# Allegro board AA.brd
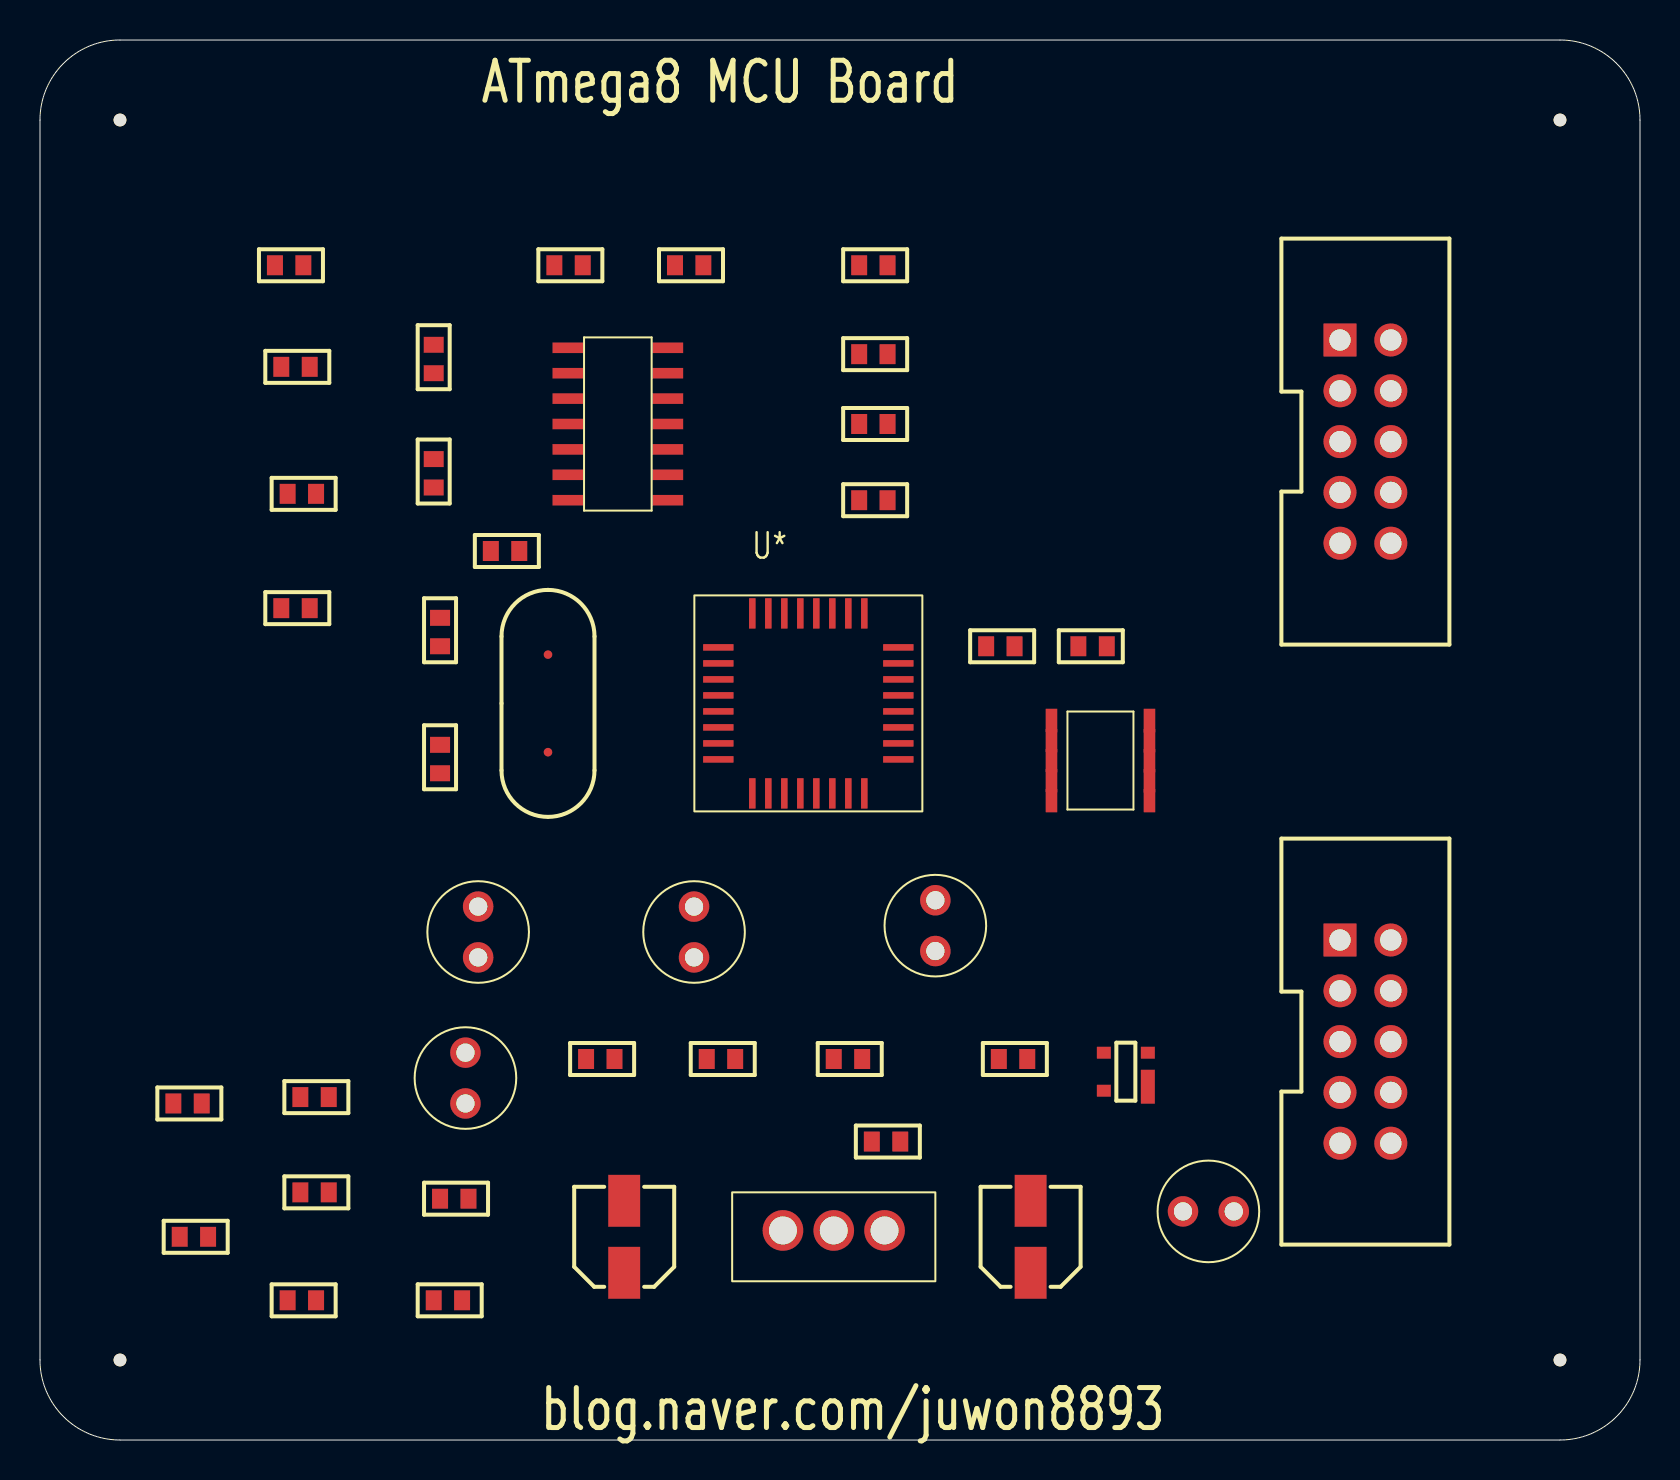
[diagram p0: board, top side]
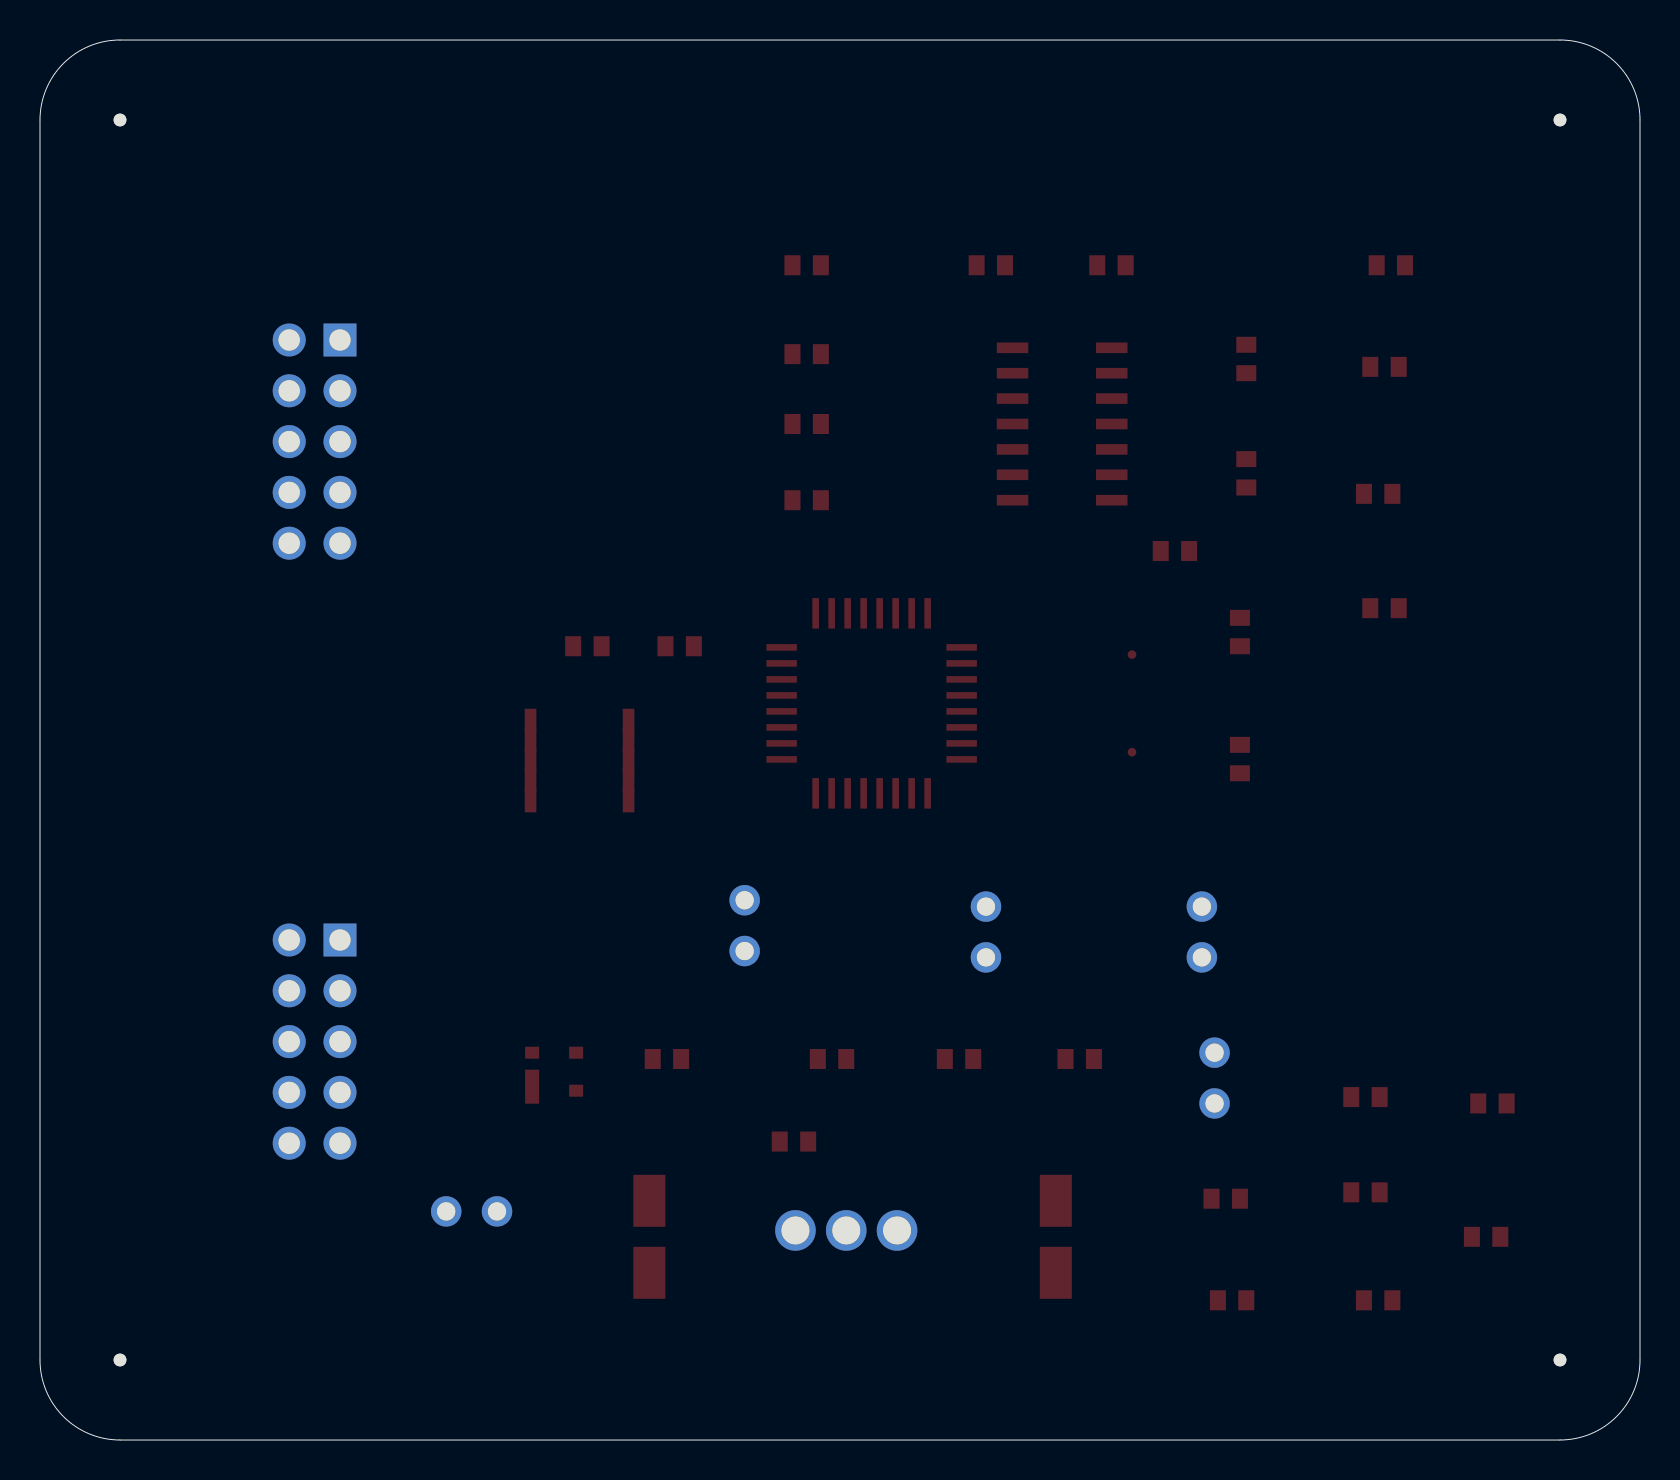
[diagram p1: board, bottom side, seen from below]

Outline 80 x 70 mm; copper layers: TOP, BOTTOM. Coordinates in mm from the lower left corner of the outline.
Outline path: 0,66 0,4 arc(1.17,1.17) 4,0 76,0 arc(78.83,1.17) 80,4 80,66 arc(78.83,68.83) 76,70 4,70 arc(1.17,68.83) 0,66

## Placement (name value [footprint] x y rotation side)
C1  0.1uF  [R]  19.68 53.34 90 top
C2  0.1uF  [R]  19.68 47.62 90 top
C3  220uF/16V  [D55]  49.53 10.16 270 top
C4  220uF/16V  [D55]  29.21 10.16 270 top
D1  LED  [CAP196]  21.91 24.13 0 top
D2  LED  [CAP196]  44.77 24.45 0 top
D3  LED  [CAP196]  32.7 24.13 0 top
D4  LED  [CAP196]  21.27 16.83 0 top
D5  LED  [CAP196]  57.15 11.43 270 top
J1  CON10  [BH2X5]  65 25 0 top
J2  CON10  [BH2X5]  65 55 0 top
NOREF  -  []  4 0 90 top
NOREF#2  -  [unnamed#2]  76 66 0 top
NOREF#3  -  []  76 0 90 top
NOREF#4  -  []  76 66 0 top
NOREF#5  -  []  0 68 0 top
NOREF#6  -  [unnamed#2]  76 4 0 top
NOREF#7  -  [unnamed#2]  4 4 0 top
NOREF#8  -  []  76 0 90 top
NOREF#9  -  [unnamed#2]  4 66 0 top
NOREF#10  -  []  76 66 90 top
R1  1K  [R]  47.94 19.05 0 top
R2  20pF  [R]  20 39.69 90 top
R3  01.uP  [R]  53.34 39.69 180 top
R4  01.uP  [R]  47.31 39.69 0 top
R5  20pF  [R]  20 33.34 90 top
R6  330  [R]  27.3 19.05 0 top
R7  330  [R]  39.69 19.05 0 top
R8  330  [R]  33.34 19.05 0 top
R9  1K  [R]  25.72 58.74 0 top
R10  1K  [R]  31.75 58.74 0 top
R11  1K  [R]  40.96 58.74 0 top
R12  1K  [R]  22.54 44.45 0 top
R13  10  [R]  12.06 53.66 0 top
R14  10  [R]  12.38 47.31 0 top
R15  10  [R]  40.96 46.99 0 top
R16  0.1uF  [R]  40.96 50.8 0 top
R17  100K  [R]  40.96 54.29 0 top
R18  100K  [R]  11.75 58.74 0 top
R19  100K  [R]  12.06 41.59 0 top
R20  0.1uF  [R]  20 12.06 0 top
R21  0.1uF  [R]  19.68 6.99 0 top
R22  0.1uF  [R]  12.38 6.99 0 top
R23  0.1uF  [R]  13.02 12.38 0 top
R24  0.1uF  [R]  6.99 10.16 0 top
R25  0.1uF  [R]  6.67 16.83 0 top
R26  820  [R]  41.59 14.92 0 top
R27  330  [R]  13.02 17.14 0 top
U1  Atmega8  [TQFP32]  38.42 36.83 0 top
U2  MIC811  [SOT-143]  54.29 18.41 90 top
U3  -  [ADM101E]  53.02 33.97 0 top
U4  -  [LM2902]  28.89 50.8 0 top
U5  LM7805  [TO220AB]  42.23 10.48 0 top
Y1  16MHz  [CRYSTAL]  25.4 36.83 90 top

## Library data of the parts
C1 C2 R2-R5 R16 R20-R25 = CAP NP
C3 C4 = CAPACITOR POL
D1 = LED_0: Tolerance: ***; User Part Number: ***
D2 = LED_1: Tolerance: ***; User Part Number: ***
D3 = LED_2: Tolerance: ***; User Part Number: ***
D4 = LED_3: Tolerance: ***; User Part Number: ***
D5 = LED_4: Tolerance: ***; User Part Number: ***
J1 J2 = CON10
R1 R6-R15 R17-R19 R26 R27 = R
U1 = atmega8_4
U2 = MIC811_2
U3 = ADM1012_0
U4 = LM2902_0
U5 = LM7805/TO_2
Y1 = CRYSTAL

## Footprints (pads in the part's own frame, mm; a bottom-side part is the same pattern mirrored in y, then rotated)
ADM101E
  rect 0.58x1.18 smd: 1(-2.45,2) 2(-2.45,1) 3(-2.45,0) 4(-2.45,-1) 5(-2.45,-2) 6(2.45,-2) 7(2.45,-1) 8(2.45,0) 9(2.45,1) 10(2.45,2)
BH2X5
  rect 1.651x1.651 hole 1.067: 1(0,0)
  round 1.651 hole 1.067: 2(2.54,0) 3(0,-2.54) 4(2.54,-2.54) 5(0,-5.08) 6(2.54,-5.08) 7(0,-7.62) 8(2.54,-7.62) 9(0,-10.16) 10(2.54,-10.16)
CAP196
  round 1.524 hole 0.914: 1(0,0) 2(0,2.54)
CRYSTAL
  round 0.43 smd: 1(-2.44,0) 2(2.44,0)
D55
  rect 2.6x1.6 smd: 1(-1.8,0) 2(1.8,0)
LM2902
  rect 1.575x0.53 smd: 1(-2.48,3.81) 2(-2.48,2.54) 3(-2.48,1.27) 4(-2.48,0) 5(-2.48,-1.27) 6(-2.48,-2.54) 7(-2.48,-3.81) 8(2.48,-3.81) 9(2.48,-2.54) 10(2.48,-1.27) 11(2.48,0) 12(2.48,1.27) 13(2.48,2.54) 14(2.48,3.81)
R
  rect 0.8x1 smd: 1(0,0) 2(1.42,0)
SOT-143
  rect 1.7x0.7 smd: 1(-0.75,-1.1)
  rect 0.6x0.7 smd: 2(0.95,-1.1) 3(0.95,1.1) 4(-0.95,1.1)
TO220AB
  round 2.032 hole 1.397: 1(0,0) 2(-2.54,0) 3(-5.08,0)
TQFP32
  rect 1.524x0.33 smd: 1(-4.5,2.8) 2(-4.5,2) 3(-4.5,1.2) 4(-4.5,0.4) 5(-4.5,-0.4) 6(-4.5,-1.2) 7(-4.5,-2) 8(-4.5,-2.8) 17(4.5,-2.8) 18(4.5,-2) 19(4.5,-1.2) 20(4.5,-0.4) 21(4.5,0.4) 22(4.5,1.2) 23(4.5,2) 24(4.5,2.8)
  rect 0.33x1.524 smd: 9(-2.8,-4.5) 10(-2,-4.5) 11(-1.2,-4.5) 12(-0.4,-4.5) 13(0.4,-4.5) 14(1.2,-4.5) 15(2,-4.5) 16(2.8,-4.5) 25(2.8,4.5) 26(2,4.5) 27(1.2,4.5) 28(0.4,4.5) 29(-0.4,4.5) 30(-1.2,4.5) 31(-2,4.5) 32(-2.8,4.5)
unnamed#2
  round 0.635 hole 3 unplated: (0,0)

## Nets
+5V: C4.1 D5.1(ANODE) D5.2(CATHODE) R1.1 R6.1 R7.1 R8.1 R20.1 R21.1 R22.1 R23.1 R24.1 R25.1 R27.1 U1.4(VCC#4) U1.6(VCC#6) U1.18(AVCC) U2.4(VCC) U3.10(VCC) U4.4(V+) U5.3(VOUT)
+12V: C3.1 J1.1 R26.2 U5.1(VIN)
0: C1.2 C2.2 C3.2 C4.2 D4.2(CATHODE) J1.6 J1.7 J1.8 R2.2 R4.1 R5.2 R9.1 R11.1 R16.2 R17.2 R18.2 R19.2 R20.2 R21.2 R22.2 R23.2 R24.2 R25.2 R27.2 U1.3(GND#3) U1.5(GND#5) U1.21(GND#21) U2.1(GND) U3.1(GND) U3.8(SD) U4.11(V-) U5.2(GND)
#ADC1: U1.19(ADC6) U4.8(OUT) U4.10(IN-)
#ADC2: R9.2 R10.1 R10.2 U1.22(ADC7) U4.1(OUT) U4.2(IN-)
#COMP1: J2.9 U1.32(PD2(INT0))
#COMP2: J2.10 U1.1(PD3(INT1))
ADC1: J2.7
ADC2: J2.8
MISO: J1.3 U1.16(PB4)
MOSI: J1.2 U1.15(PB3)
PC0: J2.1 U1.23(PC0(ADC0))
PC1: J2.2 U1.24(PC1(ADC1))
PC2: J2.3 U1.25(PC2(ADC2))
PC3: J2.4 U1.26(PC3(ADC3))
PC4: J2.5 U1.27(PC4(ADC4/SDA))
RESET: J1.5 U1.2(PD4(XCK/TO)) U2.2(R\E\S\E\T\)
RX: J1.10 U3.6(RIN)
RXD: U1.30(PD0(RXD)) U3.4(TIN)
SCK: J1.4 U1.17(PB5)
TEMP: J2.6 U1.28(PC5(ADC5/SCL))
TX: J1.9 U3.7(TOUT)
TXD: U1.31(PD1(TXD)) U3.5(ROUT)
X1: R2.1 U1.7(PB6) Y1.2
X2: R5.1 U1.8(PB7) Y1.1
N03908: R1.2 U1.29(PC6(R\E\S\E\T\)) U2.3(M\R\)
N05120: R3.1 U3.9(C1+)
N05124: R3.2 U3.2(C1-)
N015483: R4.2 U3.3(V-)
N39465: D1.2(CATHODE) U1.9(PD5(T1))
N39475: D2.2(CATHODE) U1.10(PD6(AIN0))
N39493: D3.2(CATHODE) U1.11(PD7(T2))
N39568: D1.1(ANODE) R6.2
N39572: D2.1(ANODE) R7.2
N39576: D3.1(ANODE) R8.2
N44874: R15.2 R16.1 R17.1 U4.9(IN+)
N46340: R15.1
N48170: C1.1 R13.2 R18.1 U4.3(IN+)
N48635: R11.2 R12.1 U4.5(IN-)
N48639: C2.1 R14.2 R19.1 U4.6(IN+)
N48679: R12.2 U4.7(OUT)
N48945: R13.1
N48949: R14.1
N108500: D4.1(ANODE) R26.1

Pads without a net: U1 12 13 14 20; U4 12 13 14

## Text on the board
Ref Des/Silkscreen Top: ATmega8 MCU Board | blog.naver.com/juwon8893
